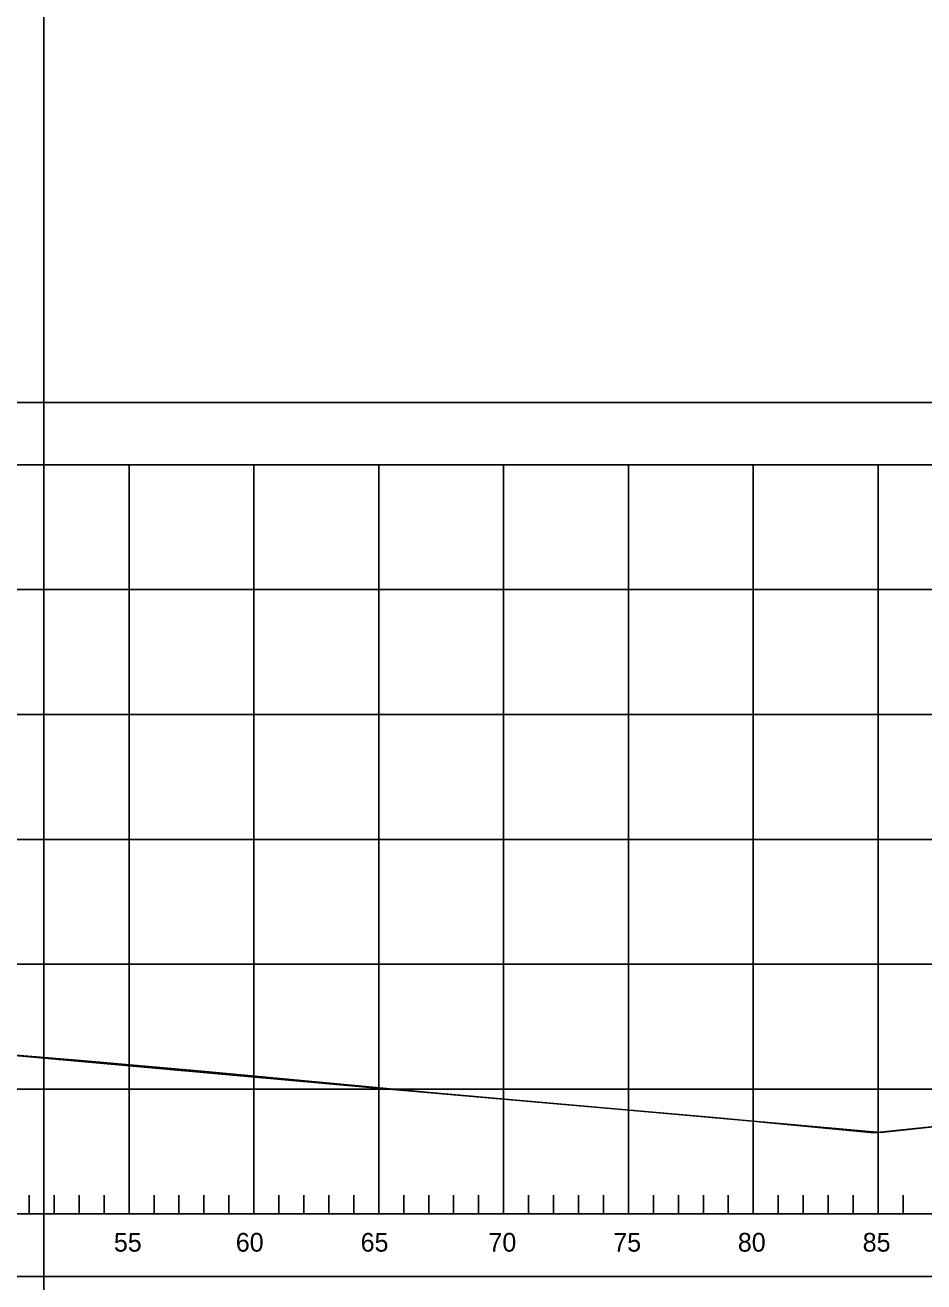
# Model space of a CAD drawing. Extents: x 1578769 to 1579225, y 724002 to 724828.
# Drawn here: x 1578890.9 to 1578926.9, y 724384.4 to 724434.8 of the extents above; entities that cross this region are included whole.
import ezdxf

# ---------------------------------------------------------------- set-up
doc = ezdxf.new("R2010")
doc.units = 0
for name, color, linetype in [('1', 7, 'Continuous'), ('Default', 7, 'Continuous'), ('Old_Level_1', 7, 'Continuous'), ('Old_Level_41', 7, 'Continuous'), ('Old_Level_42', 7, 'Continuous'), ('R_Exist Surface', 7, 'Continuous')]:
    doc.layers.add(name, color=color, linetype=linetype)

msp = doc.modelspace()

# ---------------------------------------------------------------- linework, layer by layer
at = {"layer": 'Default'}
for p, q in [((1578891.62, 724578.446), (1578891.62, 724328.446)), ((1578840.032, 724387.146), (1579140.032, 724387.146))]:
    msp.add_line(p, q, dxfattribs=at)
msp.add_lwpolyline([(1578840.032, 724407.278), (1578843.972, 724407.183), (1578868.722, 724406.957), (1578870.692, 724406.938), (1578871.022, 724406.546), (1578881.302, 724394.253), (1578887.042, 724393.796), (1578904.532, 724392.22), (1578918.752, 724390.976), (1578924.862, 724390.388), (1578951.062, 724393.135), (1578979.152, 724396.133), (1578991.892, 724397.482), (1578996.872, 724398.009), (1579008.382, 724399.253), (1579066.252, 724403.439), (1579074.562, 724404.146)], dxfattribs=at)
at = {"layer": 'Old_Level_1'}
msp.add_lwpolyline([(1578815.032, 724419.646), (1578942.532, 724419.646), (1578942.532, 724384.646), (1578815.032, 724384.646)], close=True, dxfattribs=at)
msp.add_lwpolyline([(1578820.032, 724417.146), (1578940.032, 724417.146), (1578940.032, 724387.146), (1578820.032, 724387.146)], dxfattribs=at)
at = {"layer": 'Old_Level_41'}
for p, q in [((1578895.032, 724387.146), (1578895.032, 724417.146)), ((1578900.032, 724417.146), (1578900.032, 724387.146)), ((1578905.032, 724387.146), (1578905.032, 724417.146)), ((1578910.032, 724417.146), (1578910.032, 724387.146)), ((1578915.032, 724387.146), (1578915.032, 724417.146)), ((1578920.032, 724417.146), (1578920.032, 724387.146)), ((1578925.032, 724387.146), (1578925.032, 724417.146)), ((1578925.032, 724417.146), (1578925.032, 724387.146))]:
    msp.add_line(p, q, dxfattribs=at)
for points in [[(1578940.032, 724412.146), (1578820.032, 724412.146)], [(1578940.032, 724407.146), (1578820.032, 724407.146)], [(1578820.032, 724402.146), (1578940.032, 724402.146)], [(1578940.032, 724397.146), (1578820.032, 724397.146)], [(1578820.032, 724392.146), (1578940.032, 724392.146)]]:
    msp.add_lwpolyline(points, dxfattribs=at)
at = {"layer": 'Old_Level_42'}
for p, q in [((1578891.032, 724387.896), (1578891.032, 724387.146)), ((1578892.032, 724387.896), (1578892.032, 724387.146)), ((1578893.032, 724387.896), (1578893.032, 724387.146)), ((1578894.032, 724387.896), (1578894.032, 724387.146)), ((1578896.032, 724387.896), (1578896.032, 724387.146)), ((1578897.032, 724387.896), (1578897.032, 724387.146)), ((1578898.032, 724387.896), (1578898.032, 724387.146)), ((1578899.032, 724387.896), (1578899.032, 724387.146)), ((1578901.032, 724387.896), (1578901.032, 724387.146)), ((1578902.032, 724387.896), (1578902.032, 724387.146)), ((1578903.032, 724387.896), (1578903.032, 724387.146)), ((1578904.032, 724387.896), (1578904.032, 724387.146)), ((1578906.032, 724387.896), (1578906.032, 724387.146)), ((1578907.032, 724387.896), (1578907.032, 724387.146)), ((1578908.032, 724387.896), (1578908.032, 724387.146)), ((1578909.032, 724387.896), (1578909.032, 724387.146)), ((1578911.032, 724387.896), (1578911.032, 724387.146)), ((1578912.032, 724387.896), (1578912.032, 724387.146)), ((1578913.032, 724387.896), (1578913.032, 724387.146)), ((1578914.032, 724387.896), (1578914.032, 724387.146)), ((1578916.032, 724387.896), (1578916.032, 724387.146)), ((1578917.032, 724387.896), (1578917.032, 724387.146)), ((1578918.032, 724387.896), (1578918.032, 724387.146)), ((1578919.032, 724387.896), (1578919.032, 724387.146)), ((1578921.032, 724387.896), (1578921.032, 724387.146)), ((1578922.032, 724387.896), (1578922.032, 724387.146)), ((1578923.032, 724387.896), (1578923.032, 724387.146)), ((1578924.032, 724387.896), (1578924.032, 724387.146)), ((1578926.032, 724387.896), (1578926.032, 724387.146))]:
    msp.add_line(p, q, dxfattribs=at)
at = {"layer": 'R_Exist Surface'}
msp.add_lwpolyline([(1578820.032, 724407.308), (1578840.086, 724407.296), (1578856.158, 724407.113), (1578866.051, 724406.984), (1578870.101, 724406.953), (1578871.119, 724406.484), (1578874.093, 724402.856), (1578881.072, 724394.627), (1578882.067, 724394.215), (1578883.085, 724394.135), (1578888.061, 724393.7), (1578893.092, 724393.289), (1578898.075, 724392.849), (1578907.062, 724392.008), (1578915.073, 724391.301), (1578925.131, 724390.401), (1578931.075, 724391.042), (1578938.041, 724391.763), (1578940.032, 724391.965)], dxfattribs=at)

# ---------------------------------------------------------------- texts
at = {"layer": '1'}
for s, p in [('55', (1578894.425, 724385.636)), ('60', (1578899.307, 724385.636)), ('65', (1578904.307, 724385.636)), ('70', (1578909.425, 724385.636)), ('75', (1578914.425, 724385.636)), ('80', (1578919.413, 724385.636)), ('85', (1578924.413, 724385.636))]:
    msp.add_text(s, height=0.75, dxfattribs=at).set_placement(p)

doc.saveas('drawing.dxf')
